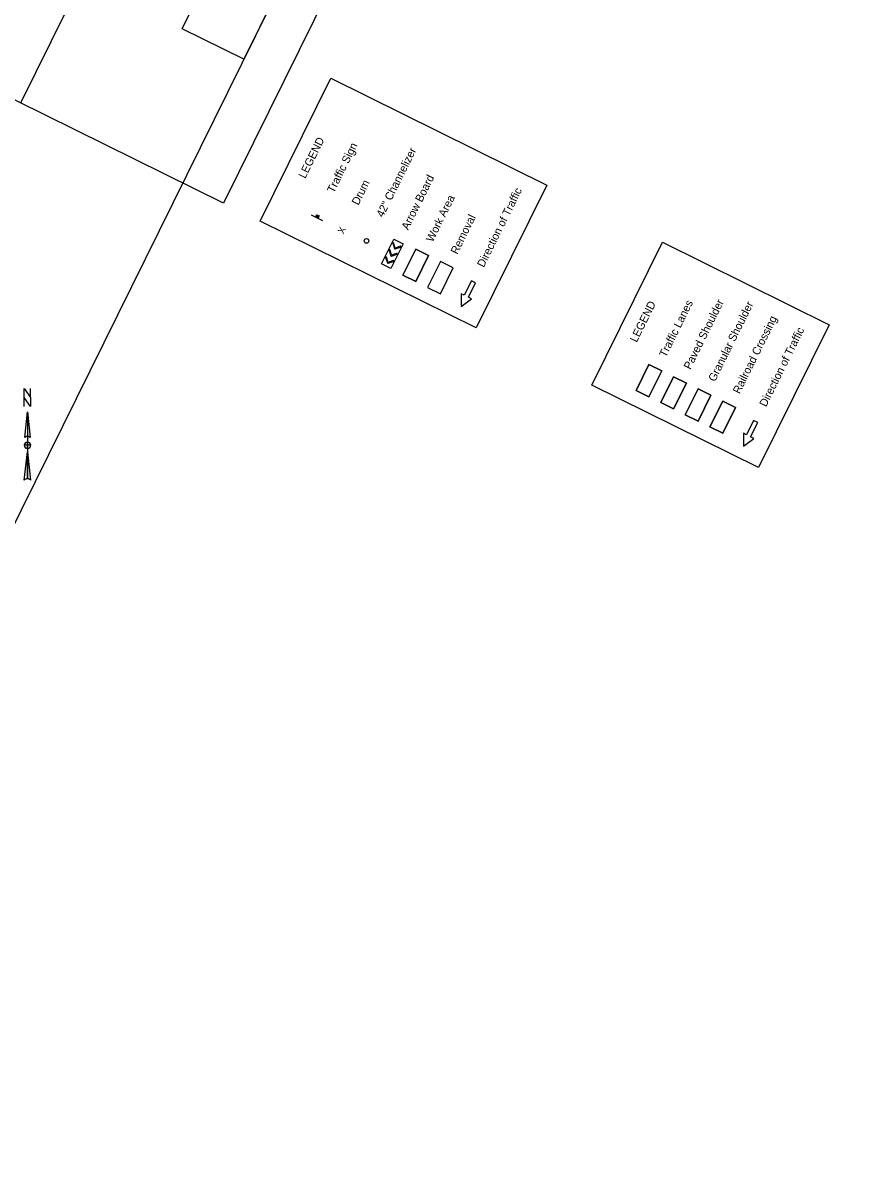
# Model space of a CAD drawing. Extents: x 14097936 to 14128734, y 8632000 to 8683104.
# Drawn here: x 14119318 to 14120232, y 8667428 to 8668694 of the extents above; entities that cross this region are included whole.
import ezdxf

# ---------------------------------------------------------------- set-up
doc = ezdxf.new("R2010")
doc.units = 0
for name, color, linetype in [('dsnCellsNorthArrow', 7, 'Continuous'), ('dsnNonPlotable', 7, 'Continuous'), ('dsnTextOverlapEven', 7, 'Continuous'), ('dsnTextOverlapOdd', 7, 'Continuous')]:
    doc.layers.add(name, color=color, linetype=linetype)

msp = doc.modelspace()

# ---------------------------------------------------------------- linework, layer by layer
at = {"layer": 'dsnCellsNorthArrow'}
for p, q in [((14119322.4, 8668269.2), (14119325.2, 8668241)), ((14119322.4, 8668269.2), (14119322.4, 8668196)), ((14119319.6, 8668241), (14119319.6, 8668241)), ((14119319.7, 8668241.3), (14119320.2, 8668241.9)), ((14119318.9, 8668194.6), (14119322.4, 8668225.6)), ((14119322.4, 8668229.1), (14119322.4, 8668229.1))]:
    msp.add_line(p, q, dxfattribs=at)
msp.add_lwpolyline([(14119325.9, 8668274.9), (14119318.9, 8668284.7), (14119318.9, 8668294.6), (14119325.9, 8668284.7)], close=True, dxfattribs=at)
for points in [[(14119318.9, 8668274.9), (14119318.9, 8668294.6), (14119325.9, 8668284.7), (14119325.9, 8668294.6)], [(14119319.6, 8668241), (14119322.4, 8668269.2), (14119322.4, 8668242.5)], [(14119322.4, 8668229.1), (14119322.4, 8668232.6), (14119318.9, 8668232.6)], [(14119325.9, 8668232.6), (14119322.4, 8668232.6), (14119322.4, 8668236.1)], [(14119322.4, 8668196), (14119322.4, 8668225.6), (14119325.9, 8668194.6)]]:
    msp.add_lwpolyline(points, dxfattribs=at)
for centre, radius, start, end in [((14119322.4, 8668232.6), 3.52, 90, 180), ((14119322.4, 8668232.6), 3.52, 180, 270), ((14119322.4, 8668238.9), 3.52, 90.0204, 143.1257), ((14119322.4, 8668238.9), 3.52, 36.8481, 90.0218), ((14119322.4, 8668232.6), 3.52, 0, 90), ((14119322.4, 8668232.6), 3.52, 270, 360), ((14119322.4, 8668190.9), 5.1, 89.9894, 133.619), ((14119322.4, 8668190.9), 5.11, 46.4021, 90.0006)]:
    msp.add_arc(centre, radius, start, end, dxfattribs=at)
at = {"layer": 'dsnNonPlotable'}
for points in [[(14118631.6, 8668945.1), (14119326.4, 8670350.2), (14120231.7, 8669902.6), (14119537, 8668497.5)], [(14119315.3, 8668607.1), (14120010, 8670012.2), (14119557.3, 8670236), (14118862.6, 8668830.9)], [(14118047.2, 8667875.9), (14118741.9, 8669281), (14119647.3, 8668833.4), (14118952.6, 8667428.2)]]:
    msp.add_lwpolyline(points, close=True, dxfattribs=at)
at = {"layer": 'dsnTextOverlapEven'}
for points in [[(14119647.3, 8668833.4), (14119559, 8668654.7), (14119491.8, 8668688), (14119580.1, 8668866.6)], [(14119491.8, 8668688), (14119580.1, 8668866.6), (14119647.3, 8668833.4), (14119559, 8668654.7)]]:
    msp.add_lwpolyline(points, close=True, dxfattribs=at)
at = {"layer": 'dsnTextOverlapOdd'}
for p, q in [((14119632.7, 8668484.5), (14119645, 8668478.4)), ((14119640.6, 8668482), (14119638.1, 8668483.2)), ((14119638.1, 8668483.1), (14119640.6, 8668481.9)), ((14119638.2, 8668483.4), (14119640.7, 8668482.1)), ((14119640.8, 8668482.3), (14119638.3, 8668483.6)), ((14119640.9, 8668482.6), (14119638.4, 8668483.8)), ((14119638.4, 8668483.7), (14119640.9, 8668482.5)), ((14119638.5, 8668484), (14119641, 8668482.8)), ((14119638.6, 8668484.3), (14119641.1, 8668483)), ((14119641.1, 8668482.9), (14119638.6, 8668484.1)), ((14119641.2, 8668483.1), (14119638.7, 8668484.4)), ((14119638.8, 8668484.5), (14119641.3, 8668483.3)), ((14119637.7, 8668482.4), (14119640.2, 8668481.2)), ((14119640.2, 8668481.1), (14119637.7, 8668482.3)), ((14119637.8, 8668482.7), (14119640.4, 8668481.4)), ((14119640.3, 8668481.3), (14119637.8, 8668482.6)), ((14119637.9, 8668482.9), (14119640.4, 8668481.6)), ((14119640.4, 8668481.5), (14119637.9, 8668482.8)), ((14119640.5, 8668481.8), (14119638, 8668483)), ((14119724.6, 8668447.4), (14119730.5, 8668449.4)), ((14119716.8, 8668431.6), (14119722.7, 8668433.6)), ((14119720.7, 8668439.5), (14119726.6, 8668441.5))]:
    msp.add_line(p, q, dxfattribs=at)
for points in [[(14119577.1, 8668477.7), (14119654.3, 8668634), (14119890.6, 8668517.2), (14119813.3, 8668360.9)], [(14119577.1, 8668477.7), (14119654.3, 8668634), (14119890.6, 8668517.2), (14119813.3, 8668360.9)], [(14119640.1, 8668480.9), (14119637.6, 8668482.2), (14119638.8, 8668484.7), (14119641.3, 8668483.5)], [(14119733.3, 8668452.9), (14119720, 8668426), (14119709.7, 8668431.1), (14119723, 8668458)], [(14119733.1, 8668418.6), (14119747.2, 8668447), (14119761.2, 8668440), (14119747.2, 8668411.7)], [(14119761.2, 8668440), (14119747.2, 8668447), (14119733.1, 8668418.6), (14119747.2, 8668411.7)], [(14119939.6, 8668298.4), (14120016.9, 8668454.7), (14120199.3, 8668364.5), (14120122, 8668208.2)], [(14119939.6, 8668298.4), (14120016.9, 8668454.7), (14120199.3, 8668364.5), (14120122, 8668208.2)], [(14119788.1, 8668426.7), (14119774, 8668433.7), (14119760, 8668405.3), (14119774.1, 8668398.4)], [(14119788.1, 8668426.7), (14119774, 8668433.7), (14119760, 8668405.3), (14119774.1, 8668398.4)], [(14119988.1, 8668292.6), (14120002.1, 8668320.9), (14120016.2, 8668313.9), (14120002.2, 8668285.6)], [(14120016.2, 8668313.9), (14120002.1, 8668320.9), (14119988.1, 8668292.6), (14120002.2, 8668285.6)], [(14120015, 8668279.3), (14120029, 8668307.6), (14120043.1, 8668300.6), (14120029.1, 8668272.3)], [(14120043.1, 8668300.6), (14120029, 8668307.6), (14120015, 8668279.3), (14120029.1, 8668272.3)], [(14120041.9, 8668266), (14120055.9, 8668294.3), (14120070, 8668287.3), (14120056, 8668259)], [(14120070, 8668287.3), (14120055.9, 8668294.3), (14120041.9, 8668266), (14120056, 8668259)], [(14120068.8, 8668252.7), (14120082.8, 8668281), (14120096.9, 8668274), (14120082.9, 8668245.7)], [(14120096.9, 8668274), (14120082.8, 8668281), (14120068.8, 8668252.7), (14120082.9, 8668245.7)]]:
    msp.add_lwpolyline(points, close=True, dxfattribs=at)
for points in [[(14119718, 8668445.7), (14119718, 8668445.7), (14119720, 8668439.8), (14119720, 8668439.8)], [(14119726.2, 8668442.5), (14119726.2, 8668442.5), (14119720.7, 8668440.4), (14119719, 8668446)], [(14119721.9, 8668453.6), (14119721.9, 8668453.6), (14119723.9, 8668447.7), (14119723.9, 8668447.7)], [(14119730.2, 8668450.4), (14119730.1, 8668450.4), (14119724.6, 8668448.3), (14119722.9, 8668453.9)], [(14119714.1, 8668437.9), (14119714.1, 8668437.8), (14119716.1, 8668432), (14119716.1, 8668431.9)], [(14119722.4, 8668434.6), (14119722.3, 8668434.6), (14119716.8, 8668432.6), (14119715.1, 8668438.2)], [(14119800.2, 8668396.7), (14119796.9, 8668398.4), (14119796.9, 8668384.4), (14119808.1, 8668392.9), (14119804.7, 8668394.5), (14119812.5, 8668410.2), (14119808, 8668412.4), (14119800.2, 8668396.7)], [(14120109, 8668244.1), (14120105.6, 8668245.8), (14120105.7, 8668231.8), (14120116.8, 8668240.2), (14120113.4, 8668241.9), (14120121.2, 8668257.6), (14120116.7, 8668259.8), (14120109, 8668244.1)]]:
    msp.add_lwpolyline(points, dxfattribs=at)
msp.add_circle((14119693.2, 8668456.1), 2.5, dxfattribs=at)
msp.add_circle((14119693.2, 8668456.1), 2.5, dxfattribs=at)
for centre, start, end in [((14119718.5, 8668445.9), 16.331, 197.4902), ((14119722.4, 8668453.8), 16.331, 197.4902), ((14119724.4, 8668447.9), 199.0813, 289.5296), ((14119730.3, 8668449.9), 288.4101, 108.5937), ((14119714.6, 8668438), 16.331, 197.4902), ((14119720.5, 8668440), 199.0813, 289.5296), ((14119722.5, 8668434.1), 288.4101, 108.5937), ((14119726.4, 8668442), 288.4101, 108.5937), ((14119716.6, 8668432.1), 199.0813, 289.5296)]:
    msp.add_arc(centre, 0.515, start, end, dxfattribs=at)

# ---------------------------------------------------------------- texts
for s, height, p in [('LEGEND', 8.75, (14119626.2, 8668523.7)), ('Traffic Sign', 8.75, (14119657.5, 8668507.8)), ('42" Channelizer ', 8.75, (14119711.3, 8668481.2)), ('Drum', 8.75, (14119684.4, 8668494.5)), ('Arrow Board', 8.75, (14119738.8, 8668467.4)), ('Direction of Traffic', 8.75, (14119821.5, 8668426.5)), ('Work Area', 8.75, (14119765.7, 8668454.1)), ('Removal', 8.75, (14119792.6, 8668440.8)), ('X', 7.5, (14119668, 8668463.2)), ('LEGEND', 8.75, (14119988.7, 8668344.5)), ('Traffic Lanes', 8.75, (14120020.7, 8668328.1)), ('Paved Shoulder', 8.75, (14120047.5, 8668314.8)), ('Granular Shoulder', 8.75, (14120074.4, 8668301.5)), ('Railroad Crossing', 8.75, (14120101.3, 8668288.2)), ('Direction of Traffic', 8.75, (14120130.3, 8668273.9))]:
    msp.add_text(s, height=height, rotation=63.6912, dxfattribs=at).set_placement(p)

doc.saveas('drawing.dxf')
